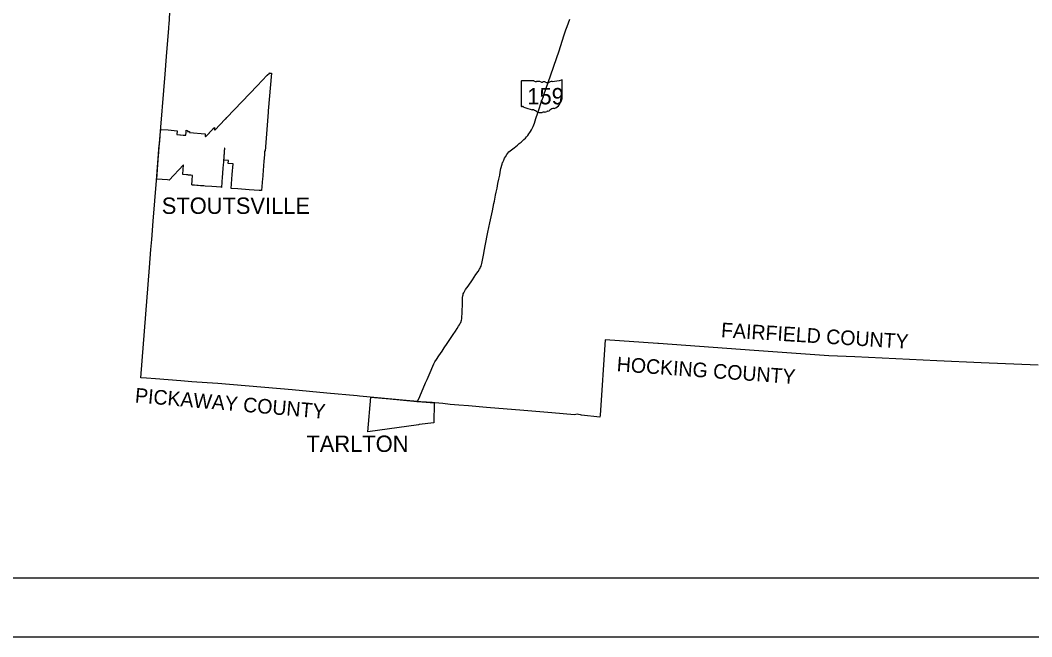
# Model space of a CAD drawing. Extents: x 1801177 to 2073177, y 78841 to 727183.
# Drawn here: x 1863539 to 1932810, y 551183 to 593373 of the extents above; entities that cross this region are included whole.
import ezdxf

# ---------------------------------------------------------------- set-up
doc = ezdxf.new("R2010")
doc.units = 0
for name, color, linetype in [('GM_X_Corporation', 7, 'Continuous'), ('GM_X_Corporation_Text', 7, 'Continuous'), ('GM_X_County', 7, 'Continuous'), ('GM_X_County_Text', 7, 'Continuous'), ('GM_X_State_Route', 7, 'Continuous'), ('GM_X_State_Shield', 7, 'Continuous'), ('SH_Border', 7, 'Continuous'), ('SH_Cut_Line', 7, 'Continuous')]:
    doc.layers.add(name, color=color, linetype=linetype)

msp = doc.modelspace()

# ---------------------------------------------------------------- linework, layer by layer
at = {"layer": 'GM_X_Corporation'}
for points in [[(1872883, 582500), (1873016, 584135), (1873028, 584285), (1873040, 584434), (1873056, 584634), (1873082, 584953), (1873090, 585052), (1873100, 585170), (1873108, 585270), (1873113, 585327), (1873127, 585492), (1873132, 585558), (1873144, 585705), (1873160, 585893), (1873161, 585903), (1873179, 585902), (1873671, 585863), (1873872, 585847), (1874290, 585815), (1874269, 585552), (1874320, 585548), (1874470, 585537), (1874483, 585536), (1874510, 585534), (1874699, 585519), (1874880, 585505), (1874883, 585537), (1874895, 585694), (1874901, 585772), (1874904, 585811), (1874907, 585843), (1874996, 585835), (1874994, 585813), (1874990, 585769), (1875057, 585763), (1875133, 585757), (1875128, 585696), (1875127, 585684), (1875139, 585684), (1876215, 585595), (1876201, 585457), (1876237, 585406), (1876242, 585411), (1876495, 585677), (1876498, 585680), (1876543, 585728), (1876748, 585943), (1876760, 585955), (1876839, 586039), (1876837, 585881), (1876858, 585861), (1876867, 585853), (1877578, 586600), (1877610, 586634), (1877695, 586723), (1879767, 588885), (1880456, 589605), (1880599, 589754), (1880609, 589765), (1880649, 589761), (1880673, 589759), (1880704, 589756), (1880737, 589753), (1880529, 587164), (1880526, 587125), (1880522, 587077), (1880305, 584405), (1880289, 584406), (1880280, 584407), (1880276, 584407), (1880256, 584152), (1880224, 583728), (1880152, 582768), (1880146, 582681), (1880145, 582674), (1880135, 582541), (1880072, 581713), (1879908, 581712), (1879228, 581767), (1878439, 581830), (1877980, 581867), (1878053, 582814), (1878113, 583556), (1878098, 583557), (1877775, 583581), (1877791, 583780), (1877492, 583802), (1877505, 583972), (1877535, 584349), (1877536, 584362), (1877554, 584609), (1877526, 584611), (1877511, 584412), (1877476, 583973), (1877432, 583424), (1877422, 583296), (1877390, 582865), (1877374, 582662), (1877321, 581920), (1877290, 581941), (1876669, 581989), (1876193, 582026), (1876123, 582032), (1875875, 582051), (1875719, 582063), (1875709, 582064), (1875634, 582070), (1875484, 582083), (1875393, 582091), (1875335, 582095), (1875287, 582100), (1875295, 582207), (1875304, 582316), (1875311, 582411), (1875312, 582426), (1875338, 582758), (1875223, 582767), (1875174, 582772), (1875056, 582782), (1875010, 582786), (1874936, 582792), (1874681, 582813), (1874683, 582843), (1874730, 583469), (1873744, 582431), (1873616, 582441), (1872901, 582499)], [(1887546, 567574), (1888854, 567455), (1890490, 567314), (1891895, 567191), (1891865, 565834), (1890866, 565699), (1890806, 565680), (1887352, 565215)]]:
    msp.add_lwpolyline(points, close=True, dxfattribs=at)
at = {"layer": 'GM_X_County'}
msp.add_lwpolyline([(1933259, 569762), (1929351, 569937), (1926317, 570076), (1920699, 570334), (1918912, 570416), (1913793, 570782), (1907251, 571250), (1907199, 571253), (1903589, 571512), (1903243, 566350), (1903234, 566210), (1901965, 566338), (1901897, 566370), (1901770, 566403), (1901676, 566405), (1901490, 566380), (1899954, 566499), (1898032, 566667), (1895480, 566882), (1894230, 566977), (1893572, 567038), (1892985, 567086), (1892469, 567142), (1891921, 567191), (1891741, 567203), (1890979, 567270), (1890754, 567288), (1889963, 567359), (1886763, 567646), (1886620, 567670), (1884542, 567858), (1882153, 568084), (1877075, 568503), (1876333, 568562), (1875301, 568635), (1874537, 568693), (1872795, 568826), (1872183, 568873), (1871788, 568907), (1872388, 576442), (1872494, 577676), (1872546, 578380), (1872648, 579623), (1872755, 581006), (1872868, 582399), (1873065, 584817), (1873075, 584916), (1873077, 584940), (1873464, 589687), (1873556, 590899), (1873710, 592841), (1873716, 592947), (1873731, 593080), (1873788, 593881)], dxfattribs=at)
at = {"layer": 'GM_X_State_Route'}
for points in [[(1896604, 583703), (1896649, 583802), (1896709, 583928), (1896769, 584037), (1896869, 584192), (1897009, 584363), (1897090, 584446), (1897273, 584567), (1897371, 584635), (1897587, 584824), (1897706, 584936), (1897835, 585036), (1897916, 585105), (1898034, 585206), (1898134, 585301), (1898218, 585385), (1898296, 585477), (1898379, 585590), (1898447, 585687), (1898493, 585757), (1898561, 585877), (1898671, 586112), (1898747, 586332), (1898853, 586648), (1898989, 587037), (1899076, 587302), (1899200, 587683), (1899263, 587871), (1899365, 588158), (1899402, 588274), (1899692, 589109), (1900435, 591284), (1900653, 591944), (1900795, 592375), (1900911, 592726), (1900993, 592946), (1901172, 593454)], [(1896014, 580990), (1896095, 581397), (1896134, 581613), (1896190, 581886), (1896246, 582190), (1896308, 582494), (1896373, 582762), (1896411, 582982), (1896450, 583218), (1896534, 583522), (1896571, 583628), (1896600, 583693), (1896604, 583703)], [(1890739, 567248), (1890755, 567285), (1890895, 567614), (1891300, 568564), (1891401, 568795), (1891537, 569107), (1891865, 569859), (1891940, 569998), (1892039, 570157), (1892216, 570418), (1892427, 570732), (1892571, 570946), (1892775, 571256), (1892956, 571532), (1893184, 571866), (1893344, 572107), (1893456, 572273), (1893562, 572435), (1893618, 572518), (1893674, 572633), (1893702, 572695), (1893756, 572851), (1893774, 572946), (1893790, 573058), (1893795, 573333), (1893800, 573479), (1893819, 573893), (1893829, 574178), (1893835, 574394), (1893847, 574519), (1893864, 574580), (1893882, 574644), (1893912, 574715), (1893981, 574848), (1894041, 574947), (1894203, 575183), (1894502, 575615), (1894750, 575969), (1894891, 576183), (1894994, 576350), (1895028, 576406), (1895067, 576478), (1895095, 576537), (1895114, 576582), (1895131, 576628), (1895157, 576722), (1895260, 577286), (1895331, 577683), (1895376, 577934), (1895566, 578865), (1895707, 579513), (1895873, 580333), (1895983, 580834), (1896014, 580990)]]:
    msp.add_lwpolyline(points, dxfattribs=at)
at = {"layer": 'GM_X_State_Shield'}
for p, q in [((1897853, 589198), (1897853, 587497)), ((1898701, 589227), (1897881, 589227)), ((1900655, 588379), (1900655, 589269)), ((1900655, 588380), (1900655, 588379))]:
    msp.add_line(p, q, dxfattribs=at)
for centre, major_axis, start_param, end_param in [((1897885, 589201), (32.5, 0), 1.712693, 3.28349), ((1898897, 589425), (315, 0), 4.042523, 4.731795), ((1899001, 588272), (1130, 0), 1.404758, 1.657858), ((1899258, 589210), (90.8, 0), 3.836095, 5.185415), ((1899391, 589014), (189, 0), 0.950623, 2.079405), ((1899635, 589283), (227, 0), 4.081561, 5.145723), ((1900036, 588707), (598, 0), 1.699011, 2.107814), ((1899657, 591546), (2971, 0), 4.814394, 5.042369), ((1900624, 589273), (31.2, 0), 6.141152, 7.989035), ((1900767, 588007), (211, 0), 2.387724, 3.262537), ((1900648, 588314), (48.3, 0), 1.883978, 3.671073), ((1900341, 588201), (290, 0), 5.934695, 6.695948), ((1900622, 588376), (33.4, 0), 5.05454, 6.418171), ((1897886, 587493), (32.7, 0), 3.00124, 4.508301), ((1897891, 587667), (250, 0), 4.665946, 4.897461), ((1897942, 587398), (90.1, 0), 0.519207, 1.627899), ((1899079, 588927), (2146, 0), 4.195997, 4.488961), ((1899823, 587894), (743, 0), 5.101752, 6.440018), ((1898440, 586732), (671, 0), 0.823519, 1.323587), ((1899166, 587390), (426, 0), 4.026481, 4.996735), ((1899412, 586802), (350, 0), 1.495662, 1.94098), ((1899443, 587263), (227, 0), 4.691044, 5.507374), ((1899648, 587098), (63.9, 0), 1.147584, 2.315152), ((1899621, 587332), (240, 0), 4.937069, 5.64225), ((1900137, 587019), (407, 0), 1.647645, 2.488434)]:
    msp.add_ellipse(centre, major_axis=major_axis, ratio=0.8, start_param=start_param, end_param=end_param, dxfattribs=at)
at = {"layer": 'SH_Border'}
msp.add_lwpolyline([(1813177, 723183), (2069177, 723183), (2069177, 555183), (1813177, 555183)], close=True, dxfattribs=at)
at = {"layer": 'SH_Cut_Line'}
msp.add_lwpolyline([(1801177, 551183), (2073177, 551183), (2073177, 727183), (1801177, 727183)], close=True, dxfattribs=at)

# ---------------------------------------------------------------- texts
at = {"layer": 'GM_X_Corporation_Text'}
for s, p in [('STOUTSVILLE', (1873231, 580121)), ('TARLTON', (1883138, 563832))]:
    msp.add_text(s, height=1120, rotation=0.00001, dxfattribs=at).set_placement(p)
at = {"layer": 'GM_X_County_Text'}
for s, rotation, p in [('FAIRFIELD COUNTY', 356.40562, (1911512, 571689)), ('HOCKING COUNTY', 355.90958, (1904364, 569353)), ('PICKAWAY COUNTY', 355.0676, (1871369, 567221))]:
    msp.add_text(s, height=1000, rotation=rotation, dxfattribs=at).set_placement(p)
at = {"layer": 'GM_X_State_Shield'}
msp.add_text('159', height=1120.7, dxfattribs=at).set_placement((1898265, 587617))

doc.saveas('drawing.dxf')
